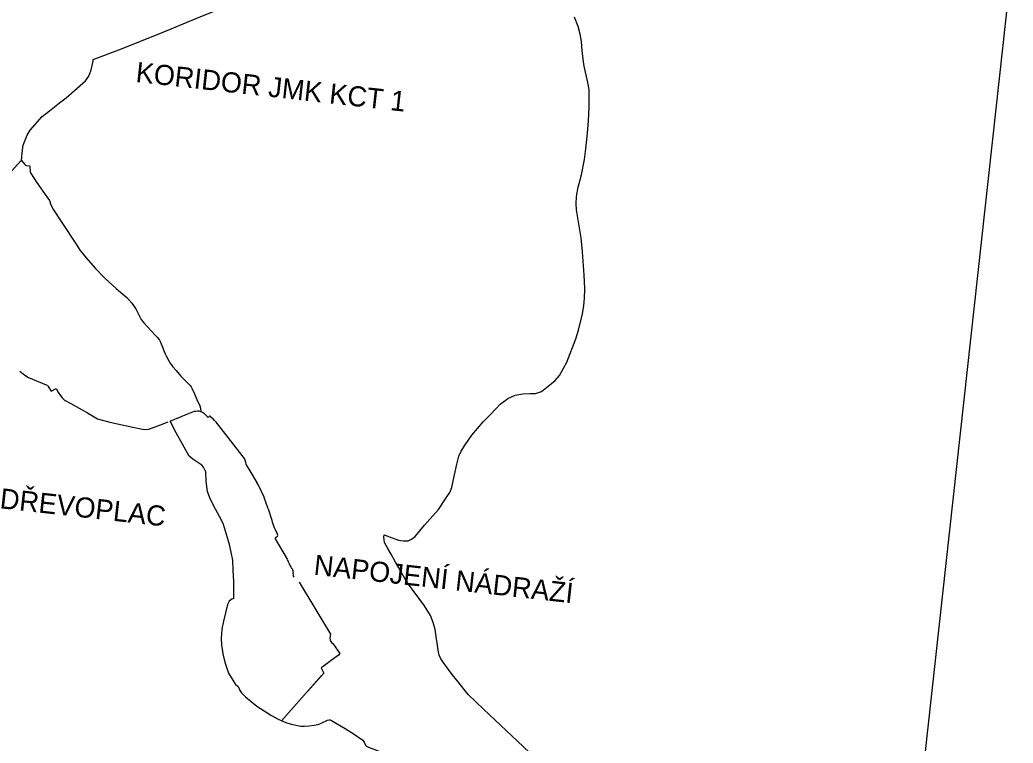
# Model space of a CAD drawing. Extents: x -678204 to -526855, y -1228851 to -1110393.
# Drawn here: x -610864 to -607907, y -1142888 to -1140735 of the extents above; entities that cross this region are included whole.
import ezdxf

# ---------------------------------------------------------------- set-up
doc = ezdxf.new("R2010")
doc.units = 0
for name, color, linetype in [('00_n_cyklo popisy detaily', 7, 'Continuous'), ('00_n_cyklo provereni vedlejsi', 7, 'Continuous'), ('00_n_cyklo prujezdne rekreacni hlavni', 7, 'Continuous'), ('00_n_cyklo prujezdne rekreacni vedlejsi', 7, 'Continuous'), ('00_n_cyklo realizace rekreacni hlavni', 7, 'Continuous'), ('00_n_cyklo trasovani rekreacni hlavni', 7, 'Continuous'), ('00_n_cyklo trasovani rekreacni vedlejsi', 7, 'Continuous'), ('_HELP', 7, 'Continuous'), ('trasy_0001', 7, 'Continuous')]:
    doc.layers.add(name, color=color, linetype=linetype)

msp = doc.modelspace()

# ---------------------------------------------------------------- linework, layer by layer
at = {"layer": '00_n_cyklo provereni vedlejsi'}
for p, q in [((-610032.9, -1142408.7), (-609939.7, -1142563.5)), ((-610085, -1142822.1), (-609966.1, -1142686.7))]:
    msp.add_line(p, q, dxfattribs=at)
for points in [[(-609939.7, -1142563.5), (-609941.2, -1142575.3), (-609940.7, -1142580.3), (-609938.8, -1142585.1), (-609936.3, -1142588.2), (-609933, -1142591.4), (-609912, -1142621.2)], [(-609912, -1142621.2), (-609915.7, -1142626), (-609941.6, -1142645.1), (-609961.1, -1142659.5), (-609967.5, -1142664.2), (-609959.8, -1142679.5), (-610006.7, -1142732.9)]]:
    msp.add_lwpolyline(points, dxfattribs=at)
at = {"layer": '00_n_cyklo prujezdne rekreacni hlavni'}
for points in [[(-610645.9, -1140853.5), (-610570, -1140824.5), (-610447.8, -1140775.9), (-610337.7, -1140730.2), (-610255.8, -1140697), (-610194.1, -1140674.9), (-610072.8, -1140635.4), (-610037.7, -1140620), (-609994.4, -1140598.8), (-609948.2, -1140572.3), (-609820.6, -1140487.9), (-609790.3, -1140462.9), (-609772.9, -1140442.2), (-609735.9, -1140385.4), (-609716.6, -1140363.2), (-609698.8, -1140353.1), (-609667.1, -1140345.3), (-609633.4, -1140342.5), (-609483.7, -1140340.5)], [(-610859.6, -1141153.6), (-610856, -1141122), (-610854.6, -1141108.2), (-610842.8, -1141078.2), (-610834, -1141063.1), (-610798.2, -1141023.2), (-610776, -1141005.6), (-610746.2, -1140982.3), (-610726.1, -1140967.5), (-610668.6, -1140916.4), (-610658.5, -1140902.6), (-610651.6, -1140884.4), (-610645.8, -1140857.8), (-610645.9, -1140853.5)], [(-610915.2, -1141213.8), (-610914.1, -1141213.4), (-610907.7, -1141209), (-610888.2, -1141184.8), (-610862.4, -1141156.2), (-610859.6, -1141153.6)], [(-610859.6, -1141153.6), (-610850.1, -1141164.6), (-610847.8, -1141167.5), (-610844.8, -1141168.7), (-610835.7, -1141169.7), (-610834.7, -1141171.1), (-610833.9, -1141188.2), (-610833, -1141190.7), (-610814.7, -1141218.5), (-610784, -1141262.4), (-610776.2, -1141272.8)], [(-610776.2, -1141272.8), (-610771.9, -1141285.6), (-610764, -1141300.6), (-610736.9, -1141341.5), (-610698.7, -1141399.4), (-610684.4, -1141421.3), (-610666.9, -1141443.8), (-610639.7, -1141474.7), (-610611.1, -1141504.3), (-610577.4, -1141535), (-610545.9, -1141561.4), (-610531.4, -1141578.2), (-610519.1, -1141595.2), (-610512.8, -1141606.8), (-610505.6, -1141622.8)], [(-610505.6, -1141622.8), (-610503.5, -1141627.2), (-610500.2, -1141631.4), (-610495.1, -1141637.2), (-610473.7, -1141660.6), (-610460.8, -1141674.5), (-610455.8, -1141679.9), (-610448.9, -1141688.8), (-610445.7, -1141694.3), (-610441.5, -1141704), (-610432.4, -1141727.1), (-610427.8, -1141737.2), (-610420.7, -1141750.1), (-610416.4, -1141757.3), (-610408.7, -1141767.6), (-610399.2, -1141779.2), (-610384.8, -1141795.5), (-610373.6, -1141807.4), (-610362.8, -1141817.3), (-610357.4, -1141823.1), (-610354.3, -1141827.6), (-610351.2, -1141833.4), (-610344.8, -1141848.6), (-610337.6, -1141865.2), (-610328.3, -1141884.3), (-610326.2, -1141890.9), (-610325.3, -1141901.8)], [(-610325.3, -1141901.8), (-610330.3, -1141900.3), (-610335.8, -1141899.8), (-610340.9, -1141900.5), (-610345.6, -1141901.1), (-610364.9, -1141908.5), (-610373.3, -1141912), (-610382, -1141915.5), (-610403.5, -1141924.4), (-610413.3, -1141928.4), (-610417, -1141929.8)], [(-610227.4, -1142457.7), (-610233.2, -1142459.3), (-610240.8, -1142465.7), (-610245.9, -1142475.7), (-610258.4, -1142524.9), (-610263.4, -1142549.1), (-610264.8, -1142576.6), (-610264.2, -1142595.2), (-610260.4, -1142621.9), (-610254, -1142647.3), (-610242.8, -1142679.3), (-610222.3, -1142713.2), (-610215.7, -1142718.7)], [(-610215.7, -1142718.7), (-610211.1, -1142725.5), (-610209.3, -1142730.9), (-610204.4, -1142738), (-610192.2, -1142750.6), (-610158.6, -1142778), (-610115.4, -1142805.5), (-610095.1, -1142816.7), (-610086.8, -1142821), (-610072.7, -1142827), (-610057.1, -1142831.8), (-610027.9, -1142837.1), (-610016.9, -1142837.5), (-610002.6, -1142836.4), (-609988.6, -1142834.5), (-609976.4, -1142832.4), (-609969.2, -1142830), (-609948.1, -1142819.7), (-609944, -1142818.6), (-609940.4, -1142818.7), (-609936.5, -1142820.2), (-609895.9, -1142844.4), (-609872.5, -1142859.3), (-609843.6, -1142878.7), (-609839.4, -1142885.2)], [(-609839.4, -1142885.2), (-609835.7, -1142894), (-609831, -1142898.2), (-609797.3, -1142911.1), (-609788.1, -1142914.9), (-609783.5, -1142917.6), (-609778.6, -1142922.7), (-609746.3, -1142961.5), (-609739.4, -1142970), (-609733.5, -1142980.5), (-609729.3, -1142988.2), (-609720.9, -1142997.9), (-609704.6, -1143015.9), (-609677.3, -1143044.8), (-609674.6, -1143046.4), (-609671.7, -1143046.6)]]:
    msp.add_lwpolyline(points, dxfattribs=at)
at = {"layer": '00_n_cyklo prujezdne rekreacni vedlejsi'}
for p, q in [((-610303.9, -1141918.5), (-610301, -1141915.6)), ((-610296.8, -1141915.6), (-610289.2, -1141923.1)), ((-610195.7, -1142040.9), (-610271.6, -1141943)), ((-610192.3, -1142051.1), (-610192.3, -1142052.5)), ((-610190.4, -1142060), (-610179.7, -1142077.1)), ((-610179.7, -1142077.1), (-610158, -1142113.9)), ((-610125.6, -1142190.7), (-610132.1, -1142170.6)), ((-610125.6, -1142190.7), (-610114.7, -1142224.5)), ((-610103, -1142275.7), (-610097.2, -1142272.3)), ((-610104.1, -1142279.8), (-610068.8, -1142340)), ((-610063.6, -1142350.9), (-610061.6, -1142356.2))]:
    msp.add_line(p, q, dxfattribs=at)
for points in [[(-610859.6, -1141153.6), (-610850.1, -1141164.6), (-610847.8, -1141167.5), (-610844.8, -1141168.7), (-610835.7, -1141169.7), (-610834.7, -1141171.1), (-610833.9, -1141188.2), (-610833, -1141190.7), (-610814.7, -1141218.5), (-610784, -1141262.4), (-610776.2, -1141272.8)], [(-610776.2, -1141272.8), (-610771.9, -1141285.6), (-610764, -1141300.6), (-610736.9, -1141341.5), (-610698.7, -1141399.4), (-610684.4, -1141421.3), (-610666.9, -1141443.8), (-610639.7, -1141474.7), (-610611.1, -1141504.3), (-610577.4, -1141535), (-610545.9, -1141561.4), (-610531.4, -1141578.2), (-610519.1, -1141595.2), (-610512.8, -1141606.8), (-610505.6, -1141622.8)], [(-610505.6, -1141622.8), (-610503.5, -1141627.2), (-610500.2, -1141631.4), (-610495.1, -1141637.2), (-610473.7, -1141660.6), (-610460.8, -1141674.5), (-610455.8, -1141679.9), (-610448.9, -1141688.8), (-610445.7, -1141694.3), (-610441.5, -1141704), (-610432.4, -1141727.1), (-610427.8, -1141737.2), (-610420.7, -1141750.1), (-610416.4, -1141757.3), (-610408.7, -1141767.6), (-610399.2, -1141779.2), (-610384.8, -1141795.5), (-610373.6, -1141807.4), (-610362.8, -1141817.3), (-610357.4, -1141823.1), (-610354.3, -1141827.6), (-610351.2, -1141833.4), (-610344.8, -1141848.6), (-610337.6, -1141865.2), (-610328.3, -1141884.3), (-610326.2, -1141890.9), (-610325.3, -1141901.8)], [(-610864.2, -1141780.7), (-610849.9, -1141792.3), (-610838.4, -1141799.4), (-610786.2, -1141821.2)], [(-610786.2, -1141821.2), (-610782.1, -1141823), (-610779.7, -1141826.4), (-610771, -1141840.9), (-610756.6, -1141832.2), (-610749.7, -1141845.1), (-610738.5, -1141859.8), (-610731.5, -1141867.4), (-610712.7, -1141877)], [(-610712.7, -1141877), (-610712.7, -1141877), (-610663.4, -1141905.2), (-610632.8, -1141922.8), (-610596, -1141932.6), (-610527.6, -1141947.9), (-610498.8, -1141953.6), (-610489.6, -1141954.4), (-610480.4, -1141953.3), (-610446, -1141940.5)], [(-610325.3, -1141901.8), (-610330.3, -1141900.3), (-610335.8, -1141899.8), (-610340.9, -1141900.5), (-610345.6, -1141901.1), (-610364.9, -1141908.5), (-610373.3, -1141912), (-610382, -1141915.5), (-610403.5, -1141924.4), (-610413.3, -1141928.4), (-610417, -1141929.8)], [(-610325.3, -1141901.8), (-610330.3, -1141900.3), (-610335.8, -1141899.8), (-610340.9, -1141900.5), (-610345.6, -1141901.1), (-610364.9, -1141908.5), (-610373.3, -1141912), (-610382, -1141915.5), (-610403.5, -1141924.4), (-610413.3, -1141928.4), (-610416.9, -1141929.7)], [(-610303.9, -1141918.5), (-610304.9, -1141917.4), (-610314.7, -1141908.3), (-610321, -1141903.9), (-610325.3, -1141901.8)], [(-610446, -1141940.5), (-610422.4, -1141931.8)], [(-610416.9, -1141929.7), (-610417, -1141929.8)]]:
    msp.add_lwpolyline(points, dxfattribs=at)
for centre, radius, start, end in [((-610298.9, -1141917.7), 3, 45.357, 135.4342), ((-610430.4, -1142066.1), 201, 37.7788, 45.357), ((-610208.3, -1142050.7), 16, 358.604, 37.7788), ((-610178.3, -1142052.9), 14, 178.604, 210.5386), ((-610417.7, -1142267.1), 301.5, 18.6603, 30.5386), ((-609831.4, -1142135.4), 296.9, 197.459, 206.4442), ((-610102.2, -1142270.1), 5.5, 335.7943, 26.4442), ((-610101.5, -1142278.3), 3, 120.3783, 210.3783), ((-610132, -1142377.1), 73.2, 20.9584, 30.3783), ((-609991.8, -1142323.6), 77, 205.0474, 217.5263), ((-610061.6, -1142377.2), 11, 347.5845, 37.5266), ((-610030.5, -1142384.1), 20.8, 167.5845, 208.8924)]:
    msp.add_arc(centre, radius, start, end, dxfattribs=at)
at = {"layer": '00_n_cyklo realizace rekreacni hlavni'}
msp.add_lwpolyline([(-610227.4, -1142457.7), (-610227.4, -1142406.7), (-610229.6, -1142373.4), (-610230.8, -1142343.3), (-610234.9, -1142320.1), (-610240.4, -1142296.8), (-610258.5, -1142237.2), (-610263.9, -1142224.5), (-610287.5, -1142180.5), (-610299.2, -1142157.4), (-610306.2, -1142138.8), (-610309.4, -1142108.4), (-610310.6, -1142080.9), (-610317.2, -1142066.8), (-610322.3, -1142060.3), (-610349.5, -1142042.5), (-610359.8, -1142033.7), (-610380.5, -1141998.4), (-610399.1, -1141964.2), (-610417, -1141929.8)], dxfattribs=at)
at = {"layer": '00_n_cyklo trasovani rekreacni hlavni'}
for points in [[(-610645.9, -1140853.5), (-610570, -1140824.5), (-610447.8, -1140775.9), (-610337.7, -1140730.2), (-610255.8, -1140697), (-610194.1, -1140674.9), (-610072.8, -1140635.4), (-610037.7, -1140620), (-609994.4, -1140598.8), (-609948.2, -1140572.3), (-609820.6, -1140487.9), (-609790.3, -1140462.9), (-609772.9, -1140442.2), (-609735.9, -1140385.4), (-609716.6, -1140363.2), (-609698.8, -1140353.1), (-609667.1, -1140345.3), (-609633.4, -1140342.5), (-609483.7, -1140340.5)], [(-610859.6, -1141153.6), (-610856, -1141122), (-610854.6, -1141108.2), (-610842.8, -1141078.2), (-610834, -1141063.1), (-610798.2, -1141023.2), (-610776, -1141005.6), (-610746.2, -1140982.3), (-610726.1, -1140967.5), (-610668.6, -1140916.4), (-610658.5, -1140902.6), (-610651.6, -1140884.4), (-610645.8, -1140857.8), (-610645.9, -1140853.5)], [(-610915.2, -1141213.8), (-610914.1, -1141213.4), (-610907.7, -1141209), (-610888.2, -1141184.8), (-610862.4, -1141156.2), (-610859.6, -1141153.6)], [(-610859.6, -1141153.6), (-610850.1, -1141164.6), (-610847.8, -1141167.5), (-610844.8, -1141168.7), (-610835.7, -1141169.7), (-610834.7, -1141171.1), (-610833.9, -1141188.2), (-610833, -1141190.7), (-610814.7, -1141218.5), (-610784, -1141262.4), (-610776.2, -1141272.8)], [(-610776.2, -1141272.8), (-610771.9, -1141285.6), (-610764, -1141300.6), (-610736.9, -1141341.5), (-610698.7, -1141399.4), (-610684.4, -1141421.3), (-610666.9, -1141443.8), (-610639.7, -1141474.7), (-610611.1, -1141504.3), (-610577.4, -1141535), (-610545.9, -1141561.4), (-610531.4, -1141578.2), (-610519.1, -1141595.2), (-610512.8, -1141606.8), (-610505.6, -1141622.8)], [(-610505.6, -1141622.8), (-610503.5, -1141627.2), (-610500.2, -1141631.4), (-610495.1, -1141637.2), (-610473.7, -1141660.6), (-610460.8, -1141674.5), (-610455.8, -1141679.9), (-610448.9, -1141688.8), (-610445.7, -1141694.3), (-610441.5, -1141704), (-610432.4, -1141727.1), (-610427.8, -1141737.2), (-610420.7, -1141750.1), (-610416.4, -1141757.3), (-610408.7, -1141767.6), (-610399.2, -1141779.2), (-610384.8, -1141795.5), (-610373.6, -1141807.4), (-610362.8, -1141817.3), (-610357.4, -1141823.1), (-610354.3, -1141827.6), (-610351.2, -1141833.4), (-610344.8, -1141848.6), (-610337.6, -1141865.2), (-610328.3, -1141884.3), (-610326.2, -1141890.9), (-610325.3, -1141901.8)], [(-610325.3, -1141901.8), (-610330.3, -1141900.3), (-610335.8, -1141899.8), (-610340.9, -1141900.5), (-610345.6, -1141901.1), (-610364.9, -1141908.5), (-610373.3, -1141912), (-610382, -1141915.5), (-610403.5, -1141924.4), (-610413.3, -1141928.4), (-610417, -1141929.8)], [(-610227.4, -1142457.7), (-610227.4, -1142406.7), (-610229.6, -1142373.4), (-610230.8, -1142343.3), (-610234.9, -1142320.1), (-610240.4, -1142296.8), (-610258.5, -1142237.2), (-610263.9, -1142224.5), (-610287.5, -1142180.5), (-610299.2, -1142157.4), (-610306.2, -1142138.8), (-610309.4, -1142108.4), (-610310.6, -1142080.9), (-610317.2, -1142066.8), (-610322.3, -1142060.3), (-610349.5, -1142042.5), (-610359.8, -1142033.7), (-610380.5, -1141998.4), (-610399.1, -1141964.2), (-610417, -1141929.8)], [(-610227.4, -1142457.7), (-610233.2, -1142459.3), (-610240.8, -1142465.7), (-610245.9, -1142475.7), (-610258.4, -1142524.9), (-610263.4, -1142549.1), (-610264.8, -1142576.6), (-610264.2, -1142595.2), (-610260.4, -1142621.9), (-610254, -1142647.3), (-610242.8, -1142679.3), (-610222.3, -1142713.2), (-610215.7, -1142718.7)], [(-610215.7, -1142718.7), (-610211.1, -1142725.5), (-610209.3, -1142730.9), (-610204.4, -1142738), (-610192.2, -1142750.6), (-610158.6, -1142778), (-610115.4, -1142805.5), (-610095.1, -1142816.7), (-610086.8, -1142821), (-610072.7, -1142827), (-610057.1, -1142831.8), (-610027.9, -1142837.1), (-610016.9, -1142837.5), (-610002.6, -1142836.4), (-609988.6, -1142834.5), (-609976.4, -1142832.4), (-609969.2, -1142830), (-609948.1, -1142819.7), (-609944, -1142818.6), (-609940.4, -1142818.7), (-609936.5, -1142820.2), (-609895.9, -1142844.4), (-609872.5, -1142859.3), (-609843.6, -1142878.7), (-609839.4, -1142885.2)], [(-609839.4, -1142885.2), (-609835.7, -1142894), (-609831, -1142898.2), (-609797.3, -1142911.1), (-609788.1, -1142914.9), (-609783.5, -1142917.6), (-609778.6, -1142922.7), (-609746.3, -1142961.5), (-609739.4, -1142970), (-609733.5, -1142980.5), (-609729.3, -1142988.2), (-609720.9, -1142997.9), (-609704.6, -1143015.9), (-609677.3, -1143044.8), (-609674.6, -1143046.4), (-609671.7, -1143046.6)]]:
    msp.add_lwpolyline(points, dxfattribs=at)
at = {"layer": '00_n_cyklo trasovani rekreacni vedlejsi'}
for p, q in [((-610303.9, -1141918.5), (-610301, -1141915.6)), ((-610296.8, -1141915.6), (-610289.2, -1141923.1)), ((-610195.7, -1142040.9), (-610271.6, -1141943)), ((-610192.3, -1142051.1), (-610192.3, -1142052.5)), ((-610190.4, -1142060), (-610179.7, -1142077.1)), ((-610179.7, -1142077.1), (-610158, -1142113.9)), ((-610125.6, -1142190.7), (-610132.1, -1142170.6)), ((-610125.6, -1142190.7), (-610114.7, -1142224.5)), ((-610103, -1142275.7), (-610097.2, -1142272.3)), ((-610104.1, -1142279.8), (-610068.8, -1142340)), ((-610063.6, -1142350.9), (-610061.6, -1142356.2)), ((-610032.9, -1142408.7), (-609939.7, -1142563.5)), ((-610085, -1142822.1), (-609966.1, -1142686.7))]:
    msp.add_line(p, q, dxfattribs=at)
for points in [[(-610859.6, -1141153.6), (-610850.1, -1141164.6), (-610847.8, -1141167.5), (-610844.8, -1141168.7), (-610835.7, -1141169.7), (-610834.7, -1141171.1), (-610833.9, -1141188.2), (-610833, -1141190.7), (-610814.7, -1141218.5), (-610784, -1141262.4), (-610776.2, -1141272.8)], [(-610776.2, -1141272.8), (-610771.9, -1141285.6), (-610764, -1141300.6), (-610736.9, -1141341.5), (-610698.7, -1141399.4), (-610684.4, -1141421.3), (-610666.9, -1141443.8), (-610639.7, -1141474.7), (-610611.1, -1141504.3), (-610577.4, -1141535), (-610545.9, -1141561.4), (-610531.4, -1141578.2), (-610519.1, -1141595.2), (-610512.8, -1141606.8), (-610505.6, -1141622.8)], [(-610505.6, -1141622.8), (-610503.5, -1141627.2), (-610500.2, -1141631.4), (-610495.1, -1141637.2), (-610473.7, -1141660.6), (-610460.8, -1141674.5), (-610455.8, -1141679.9), (-610448.9, -1141688.8), (-610445.7, -1141694.3), (-610441.5, -1141704), (-610432.4, -1141727.1), (-610427.8, -1141737.2), (-610420.7, -1141750.1), (-610416.4, -1141757.3), (-610408.7, -1141767.6), (-610399.2, -1141779.2), (-610384.8, -1141795.5), (-610373.6, -1141807.4), (-610362.8, -1141817.3), (-610357.4, -1141823.1), (-610354.3, -1141827.6), (-610351.2, -1141833.4), (-610344.8, -1141848.6), (-610337.6, -1141865.2), (-610328.3, -1141884.3), (-610326.2, -1141890.9), (-610325.3, -1141901.8)], [(-610864.2, -1141780.7), (-610849.9, -1141792.3), (-610838.4, -1141799.4), (-610786.2, -1141821.2)], [(-610786.2, -1141821.2), (-610782.1, -1141823), (-610779.7, -1141826.4), (-610771, -1141840.9), (-610756.6, -1141832.2), (-610749.7, -1141845.1), (-610738.5, -1141859.8), (-610731.5, -1141867.4), (-610712.7, -1141877)], [(-610712.7, -1141877), (-610712.7, -1141877), (-610663.4, -1141905.2), (-610632.8, -1141922.8), (-610596, -1141932.6), (-610527.6, -1141947.9), (-610498.8, -1141953.6), (-610489.6, -1141954.4), (-610480.4, -1141953.3), (-610446, -1141940.5)], [(-610325.3, -1141901.8), (-610330.3, -1141900.3), (-610335.8, -1141899.8), (-610340.9, -1141900.5), (-610345.6, -1141901.1), (-610364.9, -1141908.5), (-610373.3, -1141912), (-610382, -1141915.5), (-610403.5, -1141924.4), (-610413.3, -1141928.4), (-610417, -1141929.8)], [(-610325.3, -1141901.8), (-610330.3, -1141900.3), (-610335.8, -1141899.8), (-610340.9, -1141900.5), (-610345.6, -1141901.1), (-610364.9, -1141908.5), (-610373.3, -1141912), (-610382, -1141915.5), (-610403.5, -1141924.4), (-610413.3, -1141928.4), (-610416.9, -1141929.7)], [(-610303.9, -1141918.5), (-610304.9, -1141917.4), (-610314.7, -1141908.3), (-610321, -1141903.9), (-610325.3, -1141901.8)], [(-610446, -1141940.5), (-610422.4, -1141931.8)], [(-610416.9, -1141929.7), (-610417, -1141929.8)], [(-609939.7, -1142563.5), (-609941.2, -1142575.3), (-609940.7, -1142580.3), (-609938.8, -1142585.1), (-609936.3, -1142588.2), (-609933, -1142591.4), (-609912, -1142621.2)], [(-609912, -1142621.2), (-609915.7, -1142626), (-609941.6, -1142645.1), (-609961.1, -1142659.5), (-609967.5, -1142664.2), (-609959.8, -1142679.5), (-610006.7, -1142732.9)]]:
    msp.add_lwpolyline(points, dxfattribs=at)
for centre, radius, start, end in [((-610298.9, -1141917.7), 3, 45.357, 135.4342), ((-610430.4, -1142066.1), 201, 37.7788, 45.357), ((-610208.3, -1142050.7), 16, 358.604, 37.7788), ((-610178.3, -1142052.9), 14, 178.604, 210.5386), ((-610417.7, -1142267.1), 301.5, 18.6603, 30.5386), ((-609831.4, -1142135.4), 296.9, 197.459, 206.4442), ((-610102.2, -1142270.1), 5.5, 335.7943, 26.4442), ((-610101.5, -1142278.3), 3, 120.3783, 210.3783), ((-610132, -1142377.1), 73.2, 20.9584, 30.3783), ((-609991.8, -1142323.6), 77, 205.0474, 217.5263), ((-610061.6, -1142377.2), 11, 347.5845, 37.5266), ((-610030.5, -1142384.1), 20.8, 167.5845, 208.8924)]:
    msp.add_arc(centre, radius, start, end, dxfattribs=at)
at = {"layer": '_HELP'}
msp.add_lwpolyline([(-612622, -1140011.8), (-607907.5, -1140529.5), (-608276.1, -1143887), (-612990.7, -1143369.3)], close=True, dxfattribs=at)
at = {"layer": 'trasy_0001'}
msp.add_lwpolyline([(-609330, -1142932.1), (-609399.4, -1142866), (-609484, -1142787.2), (-609529.8, -1142742.9), (-609542.1, -1142728), (-609559.7, -1142705.6), (-609568.5, -1142694.2), (-609577, -1142683.3), (-609599, -1142654.2), (-609611.1, -1142637.6), (-609615.6, -1142626.6), (-609619.5, -1142611.4), (-609628.4, -1142550.2), (-609633.9, -1142528.7), (-609641.9, -1142508.4), (-609660.2, -1142479.5), (-609713.6, -1142406.9), (-609736.6, -1142366.1), (-609746.2, -1142349.3), (-609758.9, -1142325.6), (-609769.2, -1142308.9), (-609778.9, -1142290.9), (-609781.2, -1142275.1), (-609780, -1142268.5), (-609764.2, -1142274.2), (-609737.4, -1142283.5), (-609722.9, -1142285.6), (-609708.5, -1142286.2), (-609698.1, -1142280.6), (-609687.2, -1142272.6), (-609660.2, -1142239.7), (-609617.8, -1142192.2), (-609592.9, -1142155.4), (-609584.4, -1142142.3), (-609578.1, -1142127.4), (-609575.1, -1142112.5), (-609563.8, -1142057.4), (-609557.4, -1142033.7), (-609550.9, -1142018.9), (-609539, -1141999.8), (-609518.6, -1141971.2), (-609484.8, -1141931.9), (-609467.5, -1141913.9), (-609445.5, -1141891), (-609434.1, -1141878.7), (-609423.9, -1141871.5), (-609411.4, -1141862.2), (-609389.9, -1141852.7), (-609367.3, -1141848.7), (-609344.7, -1141847.1), (-609329.2, -1141847.5), (-609311.1, -1141841.2), (-609281.2, -1141817.4), (-609270.9, -1141808.2), (-609257.8, -1141794), (-609235.7, -1141753.6), (-609209, -1141684.4), (-609201.1, -1141659.1), (-609189.7, -1141610.5), (-609185.1, -1141585.6), (-609183.2, -1141563.4), (-609182.4, -1141536.4), (-609182.5, -1141533.5), (-609184.4, -1141495.5), (-609189.5, -1141425.7), (-609193.1, -1141384.4), (-609207.3, -1141300.9), (-609208.1, -1141283), (-609206.9, -1141261.2), (-609202.2, -1141233), (-609192.5, -1141196.5), (-609183.9, -1141150.9), (-609179.5, -1141119.5), (-609174.1, -1141072), (-609171.4, -1141035.6), (-609169.5, -1140995.3), (-609169.1, -1140962.4), (-609169.9, -1140942.5), (-609173.3, -1140921.4), (-609184.1, -1140873.1), (-609186.9, -1140860.4), (-609190.7, -1140826.2), (-609192.5, -1140799.5), (-609195.9, -1140777.7), (-609202.1, -1140755.1), (-609213.6, -1140727.1)], dxfattribs=at)

# ---------------------------------------------------------------- texts
at = {"layer": '00_n_cyklo popisy detaily'}
for s, p in [('KORIDOR JMK KCT 1', (-610521.2, -1140919.8)), ('DŘEVOPLAC', (-610925.8, -1142188.7)), ('NAPOJENÍ NÁDRAŽÍ', (-609991.2, -1142386.4))]:
    msp.add_text(s, height=60, rotation=353.6836, dxfattribs=at).set_placement(p)

doc.saveas('drawing.dxf')
